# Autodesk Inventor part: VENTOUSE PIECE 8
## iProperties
Created: 2004-11
Part Number: VENTOUSE PIECE 8
Document SubType Name: Modeling
Designer: Bruno
Manufacturer: Standard
Standards Organization: Custom
Author: Bruno
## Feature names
1. Base1
